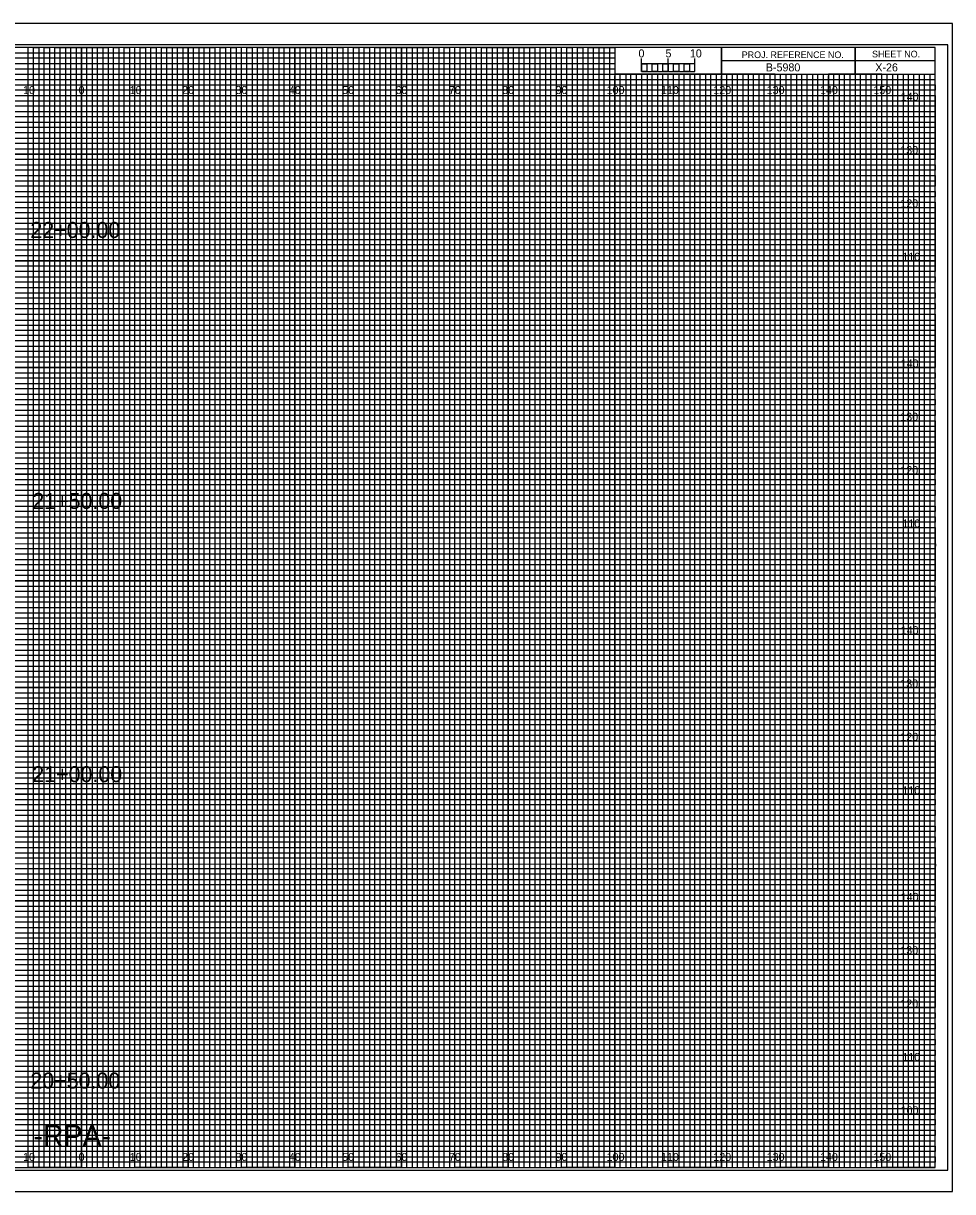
# Model space of a CAD drawing. Extents: x -13 to 323, y -5 to 1974.
# Drawn here: x 149.1 to 323.3, y 435.5 to 654.5 of the extents above; entities that cross this region are included whole.
import ezdxf

# ---------------------------------------------------------------- set-up
doc = ezdxf.new("R2010")
doc.units = 0
for name, color, linetype in [('Exist Cross Section Cell', 7, 'Continuous'), ('Exist XS Center Line Elevation Label', 7, 'Continuous'), ('Exist XS Ground Line', 7, 'Continuous'), ('Prop CMT Bridge Girder Bottom Critical Point Inside', 7, 'Continuous'), ('Prop CMT Guardrail Graphics', 7, 'Continuous'), ('Prop CMT Guardrail Widen Shoulder', 7, 'Continuous'), ('Prop CMT Pvmt Course 1', 7, 'Continuous'), ('Prop CMT Pvmt Course 2', 7, 'Continuous'), ('Prop CMT Pvmt Course 3', 7, 'Continuous'), ('Prop CMT Pvmt Surface', 7, 'Continuous'), ('Prop CMT Pvmt Surface Shoulder', 7, 'Continuous'), ('Prop CMT Shld Paved Course 1', 7, 'Continuous'), ('Prop CMT Shld Paved Course 2', 7, 'Continuous'), ('Prop CMT Shld Paved Course 3', 7, 'Continuous'), ('Prop CMT Slope Grass', 7, 'Continuous'), ('Prop CMT Subgrade Earthwork', 7, 'Continuous'), ('Scratch_Level_1', 7, 'Continuous')]:
    doc.layers.add(name, color=color, linetype=linetype)

msp = doc.modelspace()

# ---------------------------------------------------------------- linework, layer by layer
at = {"layer": 'Exist XS Center Line Elevation Label'}
for points in [[(145, 440), (155, 440), (155, 650), (165, 650), (165, 440), (175, 440), (175, 650), (185, 650), (185, 440), (195, 440), (195, 650), (205, 650), (205, 440), (215, 440), (215, 650), (225, 650), (225, 440), (235, 440), (235, 650), (245, 650), (245, 440), (255, 440), (255, 650), (259.93, 650), (260, 650), (260, 645), (264.99, 645), (264.99, 440), (275, 440), (275, 645), (285, 645), (285, 440), (295, 440), (295, 645), (305, 645), (305, 440), (315, 440), (315, 645)], [(0, 645), (275, 645)], [(0, 625), (320, 625), (320, 635), (0, 635)], [(0, 605), (320, 605), (320, 615), (0, 615)], [(0, 585), (320, 585), (320, 595), (0, 595)], [(0, 565), (320, 565), (320, 575), (0, 575)], [(0, 545), (320, 545), (320, 555), (0, 555)], [(0, 525), (320, 525), (320, 535), (0, 535)], [(0, 505), (320, 505), (320, 515), (0, 515)], [(0, 485), (320, 485), (320, 495), (0, 495)], [(0, 465), (320, 465), (320, 475), (0, 475)], [(0, 445), (320, 445), (320, 455), (0, 455)]]:
    msp.add_lwpolyline(points, dxfattribs=at)
at = {"layer": 'Exist XS Ground Line'}
for p, q in [((150, 650), (140, 650)), ((150, 440), (150, 650)), ((170, 650), (160, 650)), ((160, 650), (160, 440)), ((170, 440), (170, 650)), ((190, 650), (180, 650)), ((180, 650), (180, 440)), ((190, 440), (190, 650)), ((210, 650), (200, 650)), ((200, 650), (200, 440)), ((210, 440), (210, 650)), ((230, 650), (220, 650)), ((220, 650), (220, 440)), ((230, 440), (230, 650)), ((250, 650), (240, 650)), ((240, 650), (240, 440)), ((250, 440), (250, 650)), ((260, 650), (260, 440)), ((270, 440), (270, 645)), ((290, 645), (280, 645)), ((280, 645), (280, 440)), ((290, 440), (290, 645)), ((310, 645), (300, 645)), ((300, 645), (300, 440)), ((310, 440), (310, 645)), ((160, 440), (150, 440)), ((180, 440), (170, 440)), ((200, 440), (190, 440)), ((220, 440), (210, 440)), ((240, 440), (230, 440)), ((260, 440), (250, 440)), ((280, 440), (270, 440)), ((300, 440), (290, 440)), ((320, 440), (310, 440)), ((320, 440), (320, 440))]:
    msp.add_line(p, q, dxfattribs=at)
for points in [[(0, 640), (320, 640), (320, 630), (0, 630)], [(0, 620), (320, 620), (320, 610), (0, 610)], [(0, 600), (320, 600), (320, 590), (0, 590)], [(0, 580), (320, 580), (320, 570), (0, 570)], [(0, 560), (320, 560), (320, 550), (0, 550)], [(0, 540), (320, 540), (320, 530), (0, 530)], [(0, 520), (320, 520), (320, 510), (0, 510)], [(0, 500), (320, 500), (320, 490), (0, 490)], [(0, 480), (320, 480), (320, 470), (0, 470)], [(0, 460), (320, 460), (320, 450), (0, 450)]]:
    msp.add_lwpolyline(points, dxfattribs=at)
at = {"layer": 'Prop CMT Pvmt Course 2'}
for p, q in [((265, 645.49), (265, 647.9)), ((265, 646.9), (265, 647.9)), ((270, 645.49), (270, 647.9)), ((275, 645.49), (275, 647.9)), ((275, 646.9), (275, 647.9))]:
    msp.add_line(p, q, dxfattribs=at)
for points in [[(275, 646.9), (265, 646.9), (265, 645.49), (275, 645.49)], [(265, 646.9), (266, 646.9), (266, 645.49), (265, 645.49)], [(267, 646.9), (268, 646.9), (268, 645.49), (267, 645.49)], [(269, 646.9), (270, 646.9), (270, 645.49), (269, 645.49)], [(271, 646.9), (272, 646.9), (272, 645.49), (271, 645.49)], [(273, 646.9), (274, 646.9), (274, 645.49), (273, 645.49)]]:
    msp.add_lwpolyline(points, close=True, dxfattribs=at)
at = {"layer": 'Prop CMT Pvmt Course 3'}
msp.add_lwpolyline([(-13.4, 435.5), (323.3, 435.5), (323.3, 654.5), (-13.4, 654.5)], close=True, dxfattribs=at)
at = {"layer": 'Prop CMT Pvmt Surface'}
for p, q in [((150, 440), (150, 650)), ((160, 440), (160, 650)), ((170, 440), (170, 650)), ((180, 440), (180, 650)), ((190, 440), (190, 650)), ((200, 440), (200, 650)), ((210, 440), (210, 650)), ((220, 440), (220, 650)), ((230, 440), (230, 650)), ((240, 440), (240, 650)), ((250, 440), (250, 650)), ((260, 440), (260, 644.69)), ((270, 440), (270, 644.69)), ((280, 440), (280, 644.69)), ((290, 440), (290, 644.69)), ((300, 440), (300, 644.69)), ((310, 440), (310, 644.69)), ((0, 640), (320, 640)), ((0, 630), (320, 630)), ((0, 620), (320, 620)), ((0, 610), (320, 610)), ((0, 600), (320, 600)), ((0, 590), (320, 590)), ((0, 580), (320, 580)), ((0, 570), (320, 570)), ((0, 560), (320, 560)), ((0, 550), (320, 550)), ((0, 540), (320, 540)), ((0, 530), (320, 530)), ((0, 520), (320, 520)), ((0, 510), (320, 510)), ((0, 500), (320, 500)), ((0, 490), (320, 490)), ((0, 480), (320, 480)), ((0, 470), (320, 470)), ((0, 460), (320, 460)), ((0, 450), (320, 450))]:
    msp.add_line(p, q, dxfattribs=at)
at = {"layer": 'Prop CMT Pvmt Surface Shoulder'}
for p, q in [((323.3, 654.5), (-13.4, 654.5)), ((-13.4, 435.5), (323.3, 435.5))]:
    msp.add_line(p, q, dxfattribs=at)
at = {"layer": 'Prop CMT Shld Paved Course 1'}
for p, q in [((0, 649), (260, 649)), ((260, 649), (260, 647.98)), ((260, 647.98), (0, 647.98)), ((0, 647), (260, 647)), ((260, 647), (260, 645.89)), ((260, 645.89), (0, 645.89)), ((0, 644), (320, 644))]:
    msp.add_line(p, q, dxfattribs=at)
for points in [[(0, 643), (270, 643), (320, 643), (320, 642), (0, 642)], [(0, 641), (320, 641), (320, 639), (0, 639)], [(0, 638), (320, 638), (320, 637), (0, 636.98)], [(0, 636), (320, 636), (320, 634), (0, 634)], [(0, 633), (320, 633), (320, 632), (0, 632)], [(0, 631), (320, 631), (320, 629), (0, 629)], [(0, 628), (320, 628), (320, 627), (0, 627)], [(0, 626), (320, 626), (320, 624), (0, 624)], [(0, 623), (320, 623), (320, 622), (0, 622)], [(0, 621), (320, 621), (320, 619), (0, 619)], [(0, 618), (320, 618), (320, 617), (0, 617)], [(0, 616), (320, 616), (320, 613.95), (320, 613), (320, 612), (0, 612)], [(0, 614), (320, 614), (320, 613), (0, 613)], [(0, 611), (320, 611), (320, 609), (0, 609.03)], [(0, 609.03), (320, 609), (320, 608), (0, 608)], [(0, 607), (320, 607), (320, 606), (0, 606)], [(0, 604), (320, 604), (320, 603), (0, 603)], [(0, 602), (320, 602), (320, 601), (0, 601)], [(-0.07, 598.89), (320, 598.89), (320, 597.88), (-0.07, 597.88)], [(0, 597), (320, 597), (320, 596), (0, 596)], [(0, 594), (320, 594), (320, 593), (0, 593)], [(0, 592), (320, 592), (320, 591), (0, 591)], [(0, 589), (320, 589), (320, 588), (0, 588)], [(0, 587), (320, 587), (320, 586), (0, 586)], [(0, 584), (320, 584), (320, 583), (0, 583)], [(0, 582), (320, 582), (320, 581), (0, 581)], [(0, 579), (320, 579), (319.99, 577.98), (0, 578)], [(0, 577), (320, 577), (320, 576), (0, 576)], [(0, 574), (320, 574), (320, 573), (0, 573)], [(0, 572), (320, 572), (320, 571), (0, 571)], [(0, 569), (320, 569), (320, 568), (0, 568)], [(0, 567), (320, 567), (320, 566), (0, 566)], [(0, 564), (320, 564), (320, 563), (0, 563)], [(0, 562), (320, 562), (320, 561), (0, 561)], [(0, 559), (320, 559), (320, 558), (0, 558)], [(0, 556.99), (320.07, 556.91), (320, 556), (0, 556)], [(0, 554), (320, 554), (320, 553), (0, 553)], [(0, 552), (320, 552), (320, 551), (0, 551)], [(0, 549), (320, 549), (320, 548), (0, 548)], [(0, 547), (320, 547), (320, 546), (0, 546)], [(0, 544), (320, 544), (320, 543), (0, 543)], [(0, 542), (320, 542), (320, 541), (0, 541)], [(0, 539), (320, 539), (320, 538), (0, 538)], [(0, 537), (320, 537), (320, 536), (0, 536)], [(0, 534), (320, 534), (320, 533), (0, 533)], [(0, 532), (320, 532), (320, 531), (0, 531)], [(0, 529), (320, 529), (320, 528), (0, 528)], [(0, 527), (320, 527), (320, 526), (0, 526)], [(0, 524), (320, 524), (320, 523), (0, 523)], [(0, 522), (320, 522), (320, 521), (0, 521)], [(0, 519), (320, 519), (319.99, 517.98), (0, 518)], [(0, 517), (320, 517), (320, 516), (0, 516)], [(0, 514), (320, 514), (320, 513), (0, 513)], [(0, 512), (320, 512), (320, 511), (0, 511)], [(0, 509), (320, 509), (320, 508), (0, 508)], [(0, 507), (320, 507), (320, 506), (0, 506)], [(0, 504), (320, 504), (320, 503), (0, 503)], [(0, 502), (320, 502), (320, 501), (0, 501)], [(0, 499), (320, 499), (320, 498), (0, 498)], [(0, 496.99), (320.07, 496.91), (320, 496), (0, 496)], [(0, 494), (320, 494), (320, 493), (0, 493)], [(0, 492), (320, 492), (320, 491), (0, 491)], [(0, 489), (320, 489), (320, 488), (0, 488)], [(0, 487), (320, 487), (320, 486), (0, 486)], [(0, 484), (320, 484), (320, 483), (0, 483)], [(0, 482), (320, 482), (320, 481), (0, 481)], [(0, 479), (320, 479), (320, 478), (0, 478)], [(0, 477), (320, 477), (320, 476), (0, 476)], [(0, 474), (320, 474), (320, 473), (0, 473)], [(0, 472), (320, 472), (320, 471), (0, 471)], [(0, 469), (320, 469), (320, 468), (0, 468)], [(0, 467), (320, 467), (320, 466), (0, 466)], [(0, 464), (320, 464), (320, 463), (0, 463)], [(0, 462), (320, 462), (320, 461), (0, 461)], [(0, 459), (320, 459), (320, 458), (0, 458)], [(0, 457), (320, 457), (320, 456), (0, 456)], [(0, 454), (320, 454), (320, 453), (0, 453)], [(0, 452), (320, 452), (320, 451), (0, 451)], [(0, 449), (320, 449), (320, 448), (0, 448)], [(0, 447), (320, 447), (320, 446), (0, 446)], [(0, 444), (320, 444), (320, 443), (0, 443)], [(0, 442), (320, 442), (320, 441), (0, 441)]]:
    msp.add_lwpolyline(points, dxfattribs=at)
at = {"layer": 'Prop CMT Shld Paved Course 2'}
for p, q in [((305, 650), (305, 645)), ((305, 645), (305, 650)), ((280, 647.5), (280, 645)), ((320, 647.49), (280, 647.49)), ((280, 645), (320, 645))]:
    msp.add_line(p, q, dxfattribs=at)
for points in [[(320, 650), (0, 650), (0, 440), (320, 440)], [(280, 650), (260, 650), (260, 645.03), (280, 645.03)], [(320, 650), (280, 650), (280, 645), (320, 645)]]:
    msp.add_lwpolyline(points, close=True, dxfattribs=at)
at = {"layer": 'Prop CMT Shld Paved Course 3'}
for p, q in [((267, 645), (266.01, 645)), ((266.01, 645), (266.01, 440)), ((267, 440), (267, 645)), ((269, 645), (268, 645)), ((268, 645), (268, 440)), ((269, 440), (269, 645)), ((266.01, 440), (265, 440)), ((268, 440), (267, 440))]:
    msp.add_line(p, q, dxfattribs=at)
for points in [[(150, 440), (151, 440), (151, 650), (152, 650), (152, 440)], [(152, 440), (153, 440), (153, 650), (154, 650), (154, 440)], [(155, 440), (156, 440), (156, 650), (157, 650), (157, 440)], [(157, 440), (158, 440), (158, 650), (159, 650), (159, 440)], [(160, 440), (161, 440), (161, 650), (162, 650), (162, 440)], [(162, 440), (163, 440), (163, 650), (164, 650), (164, 440)], [(165, 440), (166, 440), (166, 650), (167, 650), (167, 440)], [(167, 440), (168, 440), (168, 650), (169, 650), (169, 440)], [(170, 440), (171, 440), (171, 650), (172, 650), (172, 440)], [(172, 440), (173, 440), (173, 650), (174, 650), (174, 440)], [(175, 440), (176, 440), (176, 650), (177, 650), (177, 440)], [(177, 440), (178, 440), (178, 650), (179, 650), (179, 440)], [(180, 440), (181, 440), (181, 650), (182, 650), (182, 440)], [(182, 440), (183, 440), (183, 650), (184, 650), (184, 440)], [(185, 440), (186, 440), (186, 650), (187, 650), (187, 440)], [(187, 440), (188, 440), (188, 650), (189, 650), (189, 440)], [(190, 440), (191, 440), (191, 650), (192, 650), (192, 440)], [(192, 440), (193, 440), (193, 650), (194, 650), (194, 440)], [(195, 440), (196, 440), (196, 650), (197, 650), (197, 440)], [(197, 440), (198, 440), (198, 650), (199, 650), (199, 440)], [(200, 440), (201, 440), (201, 650), (202, 650), (202, 440)], [(202, 440), (203, 440), (203, 650), (204, 650), (204, 440)], [(205, 440), (206, 440), (206, 650), (207, 650), (207, 440)], [(207, 440), (208, 440), (208, 650), (209, 650), (209, 440)], [(210, 440), (211, 440), (211, 650), (212, 650), (212, 440)], [(212, 440), (213, 440), (213, 650), (214, 650), (214, 440)], [(215, 440), (216, 440), (216, 650), (217, 650), (217, 440)], [(217, 440), (218, 440), (218, 650), (219, 650), (219, 440)], [(220, 440), (221, 440), (221, 650), (222, 650), (222, 440)], [(222, 440), (223, 440), (223, 650), (224, 650), (224, 440)], [(225, 440), (226, 440), (226, 650), (227, 650), (227, 440)], [(227, 440), (228, 440), (228, 650), (229, 650), (229, 440)], [(230, 440), (231, 440), (231, 650), (232, 650), (232, 440)], [(232, 440), (233, 440), (233, 650), (234, 650), (234, 440)], [(235, 440), (236, 440), (236, 650), (237, 650), (237, 440)], [(237, 440), (238, 440), (238, 650), (239, 650), (239, 440)], [(240, 440), (241, 440), (241, 650), (242, 650), (242, 440)], [(242, 440), (243, 440), (243, 650), (244, 650), (244, 440)], [(245, 440), (246, 440), (246, 650), (247, 650), (247, 440)], [(247, 440), (248, 440), (248, 650), (249, 650), (249, 440)], [(250, 440), (251, 440), (251, 650), (252, 650), (252, 440)], [(252, 440), (253, 440), (253, 650), (254, 650), (254, 440)], [(255, 440), (256, 440), (256, 650), (257, 650), (257, 440)], [(257, 440), (258, 440), (258, 650), (259, 650), (259, 440)], [(260, 440), (261, 440), (261, 645), (262.02, 645), (262.02, 440)], [(262, 440), (263, 440), (263, 645), (263.99, 645), (263.99, 440)], [(270, 440), (270.98, 440), (270.98, 645), (272, 645), (272, 440)], [(272, 440), (273, 440), (273, 645), (274.05, 645), (274.05, 440)], [(275, 440), (276, 440), (276, 645), (277, 645), (277, 440)], [(277, 440), (278, 440), (278, 645), (279, 645), (279, 440)], [(280, 440), (281, 440), (281, 645), (282, 645), (282, 440)], [(282, 440), (283, 440), (283, 645), (284, 645), (284, 440)], [(285, 440), (286, 440), (286, 645), (287, 645), (287, 440)], [(287, 440), (288, 440), (288, 645), (289, 645), (289, 440)], [(290, 440), (291, 440), (291, 645), (292, 645), (292, 440)], [(292, 440), (293, 440), (293, 645), (294, 645), (294, 440)], [(295, 440), (296, 440), (296, 645), (297, 645), (297, 440)], [(297, 440), (298, 440), (298, 645), (299, 645), (299, 440)], [(300, 440), (301, 440), (301, 645), (302, 645), (302, 440)], [(302, 440), (303, 440), (303, 645), (304, 645), (304, 440)], [(305, 440), (306, 440), (306, 645), (307, 645), (307, 440)], [(307, 440), (308, 440), (308, 645), (309, 645), (309, 440)], [(310, 440), (311, 440), (311, 645), (312, 645), (312, 440)], [(312, 440), (313, 440), (313, 645), (314, 645), (314, 440)], [(315, 440), (316, 440), (316, 645), (317, 645), (317, 440)], [(317, 440), (318, 440), (318, 645), (319, 645), (319, 440)]]:
    msp.add_lwpolyline(points, dxfattribs=at)
at = {"layer": 'Prop CMT Subgrade Earthwork'}
msp.add_lwpolyline([(-10.8, 439.5), (322.4, 439.5), (322.4, 650.5), (-10.8, 650.5)], close=True, dxfattribs=at)

# ---------------------------------------------------------------- texts
at = {"layer": 'Exist Cross Section Cell'}
for s, p in [('10', (149.04, 641.25)), ('0', (159.45, 641.25)), ('0', (159.45, 641.25)), ('10', (169.04, 641.25)), ('20', (178.86, 641.25)), ('30', (188.86, 641.25)), ('40', (198.86, 641.25)), ('50', (208.86, 641.25)), ('60', (218.86, 641.25)), ('70', (228.86, 641.25)), ('80', (238.86, 641.25)), ('90', (248.86, 641.25)), ('100', (258.44, 641.25)), ('110', (268.62, 641.25)), ('120', (278.44, 641.25)), ('130', (288.44, 641.25)), ('140', (298.44, 641.25)), ('150', (308.44, 641.25)), ('10', (149.04, 441.25)), ('0', (159.45, 441.25)), ('0', (159.45, 441.25)), ('10', (169.04, 441.25)), ('20', (178.86, 441.25)), ('30', (188.86, 441.25)), ('40', (198.86, 441.25)), ('50', (208.86, 441.25)), ('60', (218.86, 441.25)), ('70', (228.86, 441.25)), ('80', (238.86, 441.25)), ('90', (248.86, 441.25)), ('100', (258.44, 441.25)), ('110', (268.62, 441.25)), ('120', (278.44, 441.25)), ('130', (288.44, 441.25)), ('140', (298.44, 441.25)), ('150', (308.44, 441.25))]:
    msp.add_text(s, height=1.5, dxfattribs=at).set_placement(p)
at = {"layer": 'Prop CMT Bridge Girder Bottom Critical Point Inside'}
for s, p in [('5', (269.47, 648.12)), ('10', (274.04, 648.12))]:
    msp.add_text(s, height=1.5, dxfattribs=at).set_placement(p)
at = {"layer": 'Prop CMT Guardrail Graphics'}
msp.add_text('B-5980', height=1.5, dxfattribs=at).set_placement((288.28, 645.5))
at = {"layer": 'Prop CMT Guardrail Widen Shoulder'}
msp.add_text('X-26', height=1.5, dxfattribs=at).set_placement((308.8, 645.5))
at = {"layer": 'Prop CMT Pvmt Course 1'}
for s, p in [('140', (313.57, 640)), ('130', (313.49, 630)), ('120', (313.5, 620)), ('110', (313.88, 610)), ('140', (313.57, 590)), ('130', (313.49, 580)), ('120', (313.5, 570)), ('110', (313.88, 560)), ('140', (313.57, 540)), ('130', (313.49, 530)), ('120', (313.5, 520)), ('110', (313.88, 510)), ('140', (313.57, 490)), ('130', (313.49, 480)), ('120', (313.5, 470)), ('110', (313.88, 460)), ('100', (313.55, 450))]:
    msp.add_text(s, height=1.5, dxfattribs=at).set_placement(p)
at = {"layer": 'Prop CMT Pvmt Course 2'}
msp.add_text('0', height=1.5, dxfattribs=at).set_placement((264.41, 648.12))
at = {"layer": 'Prop CMT Shld Paved Course 2'}
for s, p in [('PROJ. REFERENCE NO.', (283.77, 647.99)), ('SHEET NO.', (308.19, 648.12))]:
    msp.add_text(s, height=1.25, dxfattribs=at).set_placement(p)
at = {"layer": 'Prop CMT Slope Grass'}
for s, p in [('22+00.00', (150.41, 614.27)), ('21+50.00', (150.77, 563.48)), ('21+00.00', (150.77, 512.26)), ('20+50.00', (150.41, 454.82))]:
    msp.add_text(s, height=3, dxfattribs=at).set_placement(p)
at = {"layer": 'Scratch_Level_1'}
msp.add_text('-RPA-', height=4, dxfattribs=at).set_placement((150.97, 444))

doc.saveas('drawing.dxf')
